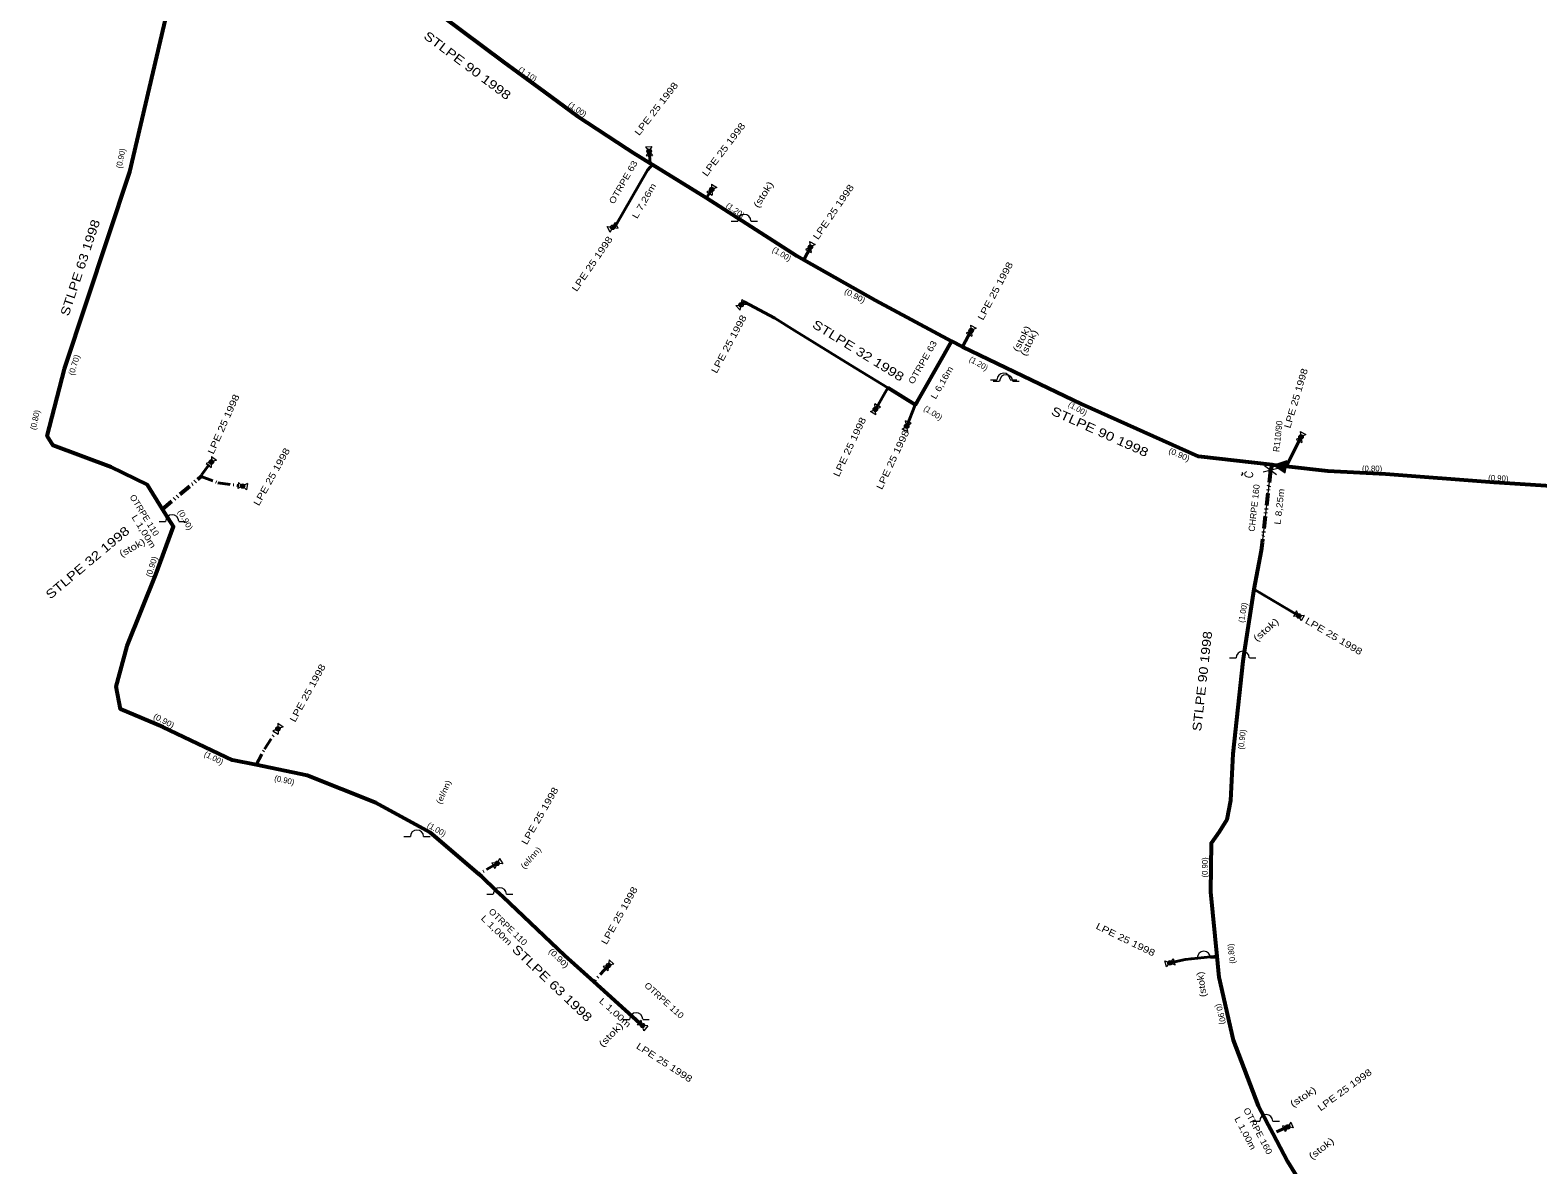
# Model space of a CAD drawing. Extents: x -648036 to -642998, y -1161549 to -1158141.
# Drawn here: x -646532.8 to -646363, y -1160970.1 to -1160842.2 of the extents above; entities that cross this region are included whole.
import ezdxf
from ezdxf.enums import TextEntityAlignment as Align

# ---------------------------------------------------------------- set-up
doc = ezdxf.new("R2010")
doc.units = 0
doc.header["$LTSCALE"] = 0.28
doc.linetypes.add('DASH_DOUBLE_DOT', pattern=[9.2, 5, -1.2, 0.3, -1.2, 0.3, -1.2])
for name, color, linetype, lineweight in [('12', 7, 'DASH_DOUBLE_DOT', 40), ('14', 7, 'Continuous', 13), ('15', 7, 'Continuous', 13), ('19', 7, 'Continuous', 13), ('8', 7, 'Continuous', 53)]:
    doc.layers.add(name, color=color, linetype=linetype, lineweight=lineweight)
for name, color, linetype in [('20', 7, 'Continuous'), ('22', 7, 'Continuous'), ('24', 7, 'Continuous'), ('25', 7, 'Continuous'), ('27', 7, 'Continuous'), ('28', 7, 'Continuous')]:
    doc.layers.add(name, color=color, linetype=linetype)

msp = doc.modelspace()

# ---------------------------------------------------------------- linework, layer by layer
at = {"layer": '12', "linetype": 'Continuous'}
for p, q in [((-646462.98, -1160857.21), (-646463.08, -1160855.87)), ((-646456.62, -1160861.15), (-646456.03, -1160860.2)), ((-646444.91, -1160866.68), (-646445.64, -1160868.12)), ((-646427.78, -1160877.92), (-646426.81, -1160876.1)), ((-646436.18, -1160882.55), (-646437.6, -1160884.97)), ((-646433.11, -1160884.48), (-646434.07, -1160886.86)), ((-646391.34, -1160891.4), (-646389.65, -1160888.08)), ((-646394.97, -1160905.24), (-646389.9, -1160908.26))]:
    msp.add_line(p, q, dxfattribs=at)
at = {"layer": '12'}
for p, q in [((-646480.19, -1160936.14), (-646482.27, -1160937.34)), ((-646467.65, -1160947.64), (-646469.3, -1160949.46)), ((-646464.09, -1160954.18), (-646463.83, -1160954.4)), ((-646391.13, -1160965.84), (-646392.83, -1160966.59))]:
    msp.add_line(p, q, dxfattribs=at)
at = {"layer": '12', "linetype": 'Continuous'}
for points in [[(-646462.7, -1160857.39), (-646463.26, -1160858), (-646466.87, -1160864.3), (-646467.19, -1160864.46)], [(-646436.18, -1160882.55), (-646440.44, -1160879.95), (-646446.71, -1160876.08), (-646448.94, -1160874.68), (-646452.36, -1160872.85), (-646452.72, -1160873.19)], [(-646399.14, -1160946.59), (-646402.7, -1160946.96), (-646404.41, -1160947.35)]]:
    msp.add_lwpolyline(points, dxfattribs=at)
at = {"layer": '12'}
for points in [[(-646513.52, -1160892.54), (-646513.47, -1160892.31), (-646512.39, -1160890.9)], [(-646513.52, -1160892.54), (-646511.67, -1160893.24), (-646508.87, -1160893.62)], [(-646507.36, -1160925.05), (-646506.41, -1160923.27), (-646504.89, -1160920.97)]]:
    msp.add_lwpolyline(points, dxfattribs=at)
at = {"layer": '14'}
for p, q in [((-646463.26, -1160858), (-646466.87, -1160864.3)), ((-646429.87, -1160878.82), (-646432.93, -1160884.17)), ((-646393.09, -1160891.84), (-646394.03, -1160900.03)), ((-646517.26, -1160897.24), (-646516.67, -1160898.18)), ((-646396.19, -1160913.36), (-646396.07, -1160912.3)), ((-646479.54, -1160939.9), (-646480.26, -1160939.22)), ((-646464.97, -1160953.38), (-646464.09, -1160954.18)), ((-646393.82, -1160964.73), (-646393.35, -1160965.61))]:
    msp.add_line(p, q, dxfattribs=at)
at = {"layer": '15'}
for p, q in [((-646463.473, -1160855.394), (-646462.762, -1160855.341)), ((-646463.473, -1160855.394), (-646462.687, -1160856.346)), ((-646462.762, -1160855.341), (-646463.398, -1160856.398)), ((-646463.398, -1160856.398), (-646462.687, -1160856.346)), ((-646455.462, -1160859.96), (-646456.598, -1160860.439)), ((-646456.067, -1160859.584), (-646455.993, -1160860.816)), ((-646456.067, -1160859.584), (-646455.462, -1160859.96)), ((-646456.598, -1160860.439), (-646455.993, -1160860.816)), ((-646453.835, -1160863.745), (-646453.1, -1160863.744)), ((-646451.614, -1160863.744), (-646450.88, -1160863.745)), ((-646467.8, -1160864.367), (-646466.581, -1160864.553)), ((-646467.482, -1160865.004), (-646467.8, -1160864.367)), ((-646467.482, -1160865.004), (-646466.898, -1160863.916)), ((-646466.581, -1160864.553), (-646466.898, -1160863.916)), ((-646444.365, -1160866.391), (-646445.455, -1160866.968)), ((-646445.455, -1160866.968), (-646444.82, -1160867.291)), ((-646445, -1160866.069), (-646444.82, -1160867.291)), ((-646445, -1160866.069), (-646444.365, -1160866.391)), ((-646453.331, -1160873.277), (-646452.11, -1160873.103)), ((-646452.842, -1160873.795), (-646453.331, -1160873.277)), ((-646452.842, -1160873.795), (-646452.598, -1160872.585)), ((-646452.11, -1160873.103), (-646452.598, -1160872.585)), ((-646426.887, -1160875.488), (-646426.733, -1160876.712)), ((-646426.887, -1160875.488), (-646426.259, -1160875.823)), ((-646426.259, -1160875.823), (-646427.361, -1160876.376)), ((-646427.361, -1160876.376), (-646426.733, -1160876.712)), ((-646424.635, -1160881.635), (-646423.9, -1160881.634)), ((-646424.345, -1160881.805), (-646423.61, -1160881.804)), ((-646422.414, -1160881.634), (-646421.68, -1160881.635)), ((-646422.124, -1160881.804), (-646421.39, -1160881.805)), ((-646438.162, -1160885.225), (-646437.038, -1160884.716)), ((-646437.548, -1160885.585), (-646438.162, -1160885.225)), ((-646437.038, -1160884.716), (-646437.652, -1160884.355)), ((-646437.548, -1160885.585), (-646437.652, -1160884.355)), ((-646434.589, -1160887.194), (-646433.552, -1160886.527)), ((-646433.928, -1160887.461), (-646434.589, -1160887.194)), ((-646433.552, -1160886.527), (-646434.212, -1160886.259)), ((-646433.928, -1160887.461), (-646434.212, -1160886.259)), ((-646389.739, -1160887.469), (-646389.561, -1160888.691)), ((-646389.739, -1160887.469), (-646389.104, -1160887.792)), ((-646389.104, -1160887.792), (-646390.195, -1160888.367)), ((-646390.195, -1160888.367), (-646389.561, -1160888.691)), ((-646511.801, -1160890.716), (-646512.978, -1160891.083)), ((-646512.366, -1160890.283), (-646512.414, -1160891.517)), ((-646512.366, -1160890.283), (-646511.801, -1160890.716)), ((-646512.978, -1160891.083), (-646512.414, -1160891.517)), ((-646396.376, -1160892.404), (-646396.199, -1160892.273)), ((-646396.322, -1160892.089), (-646396.199, -1160892.273)), ((-646392.278, -1160891.63), (-646393.901, -1160892.051)), ((-646392.43, -1160892.359), (-646393.749, -1160891.322)), ((-646509.321, -1160893.2), (-646509.417, -1160893.905)), ((-646508.323, -1160893.335), (-646509.417, -1160893.905)), ((-646508.418, -1160894.041), (-646509.321, -1160893.2)), ((-646508.323, -1160893.335), (-646508.418, -1160894.041)), ((-646518.285, -1160897.595), (-646517.55, -1160897.594)), ((-646516.064, -1160897.594), (-646515.33, -1160897.595)), ((-646390.15, -1160907.697), (-646390.515, -1160908.308)), ((-646389.649, -1160908.824), (-646390.15, -1160907.697)), ((-646389.285, -1160908.212), (-646390.515, -1160908.308)), ((-646389.285, -1160908.212), (-646389.649, -1160908.824)), ((-646397.695, -1160912.985), (-646396.96, -1160912.984)), ((-646395.474, -1160912.984), (-646394.74, -1160912.985)), ((-646504.315, -1160920.746), (-646505.464, -1160921.193)), ((-646505.464, -1160921.193), (-646504.871, -1160921.587)), ((-646504.909, -1160920.353), (-646504.871, -1160921.587)), ((-646504.909, -1160920.353), (-646504.315, -1160920.746)), ((-646490.705, -1160933.125), (-646489.97, -1160933.124)), ((-646488.484, -1160933.124), (-646487.75, -1160933.125)), ((-646480.804, -1160936.083), (-646480.449, -1160936.7)), ((-646479.576, -1160936.197), (-646480.804, -1160936.083)), ((-646479.931, -1160935.58), (-646480.449, -1160936.7)), ((-646479.931, -1160935.58), (-646479.576, -1160936.197)), ((-646481.375, -1160939.625), (-646480.64, -1160939.624)), ((-646479.154, -1160939.624), (-646478.42, -1160939.625)), ((-646404.822, -1160947.809), (-646403.998, -1160946.891)), ((-646403.84, -1160947.585), (-646403.998, -1160946.891)), ((-646402.075, -1160946.795), (-646401.34, -1160946.794)), ((-646399.854, -1160946.794), (-646399.12, -1160946.795)), ((-646467.048, -1160947.506), (-646468.252, -1160947.774)), ((-646468.252, -1160947.774), (-646467.725, -1160948.253)), ((-646467.575, -1160947.027), (-646467.725, -1160948.253)), ((-646467.575, -1160947.027), (-646467.048, -1160947.506)), ((-646404.981, -1160947.115), (-646403.84, -1160947.585)), ((-646404.822, -1160947.809), (-646404.981, -1160947.115)), ((-646466.025, -1160953.725), (-646465.29, -1160953.724)), ((-646463.804, -1160953.724), (-646463.07, -1160953.725)), ((-646463.984, -1160953.803), (-646464.445, -1160954.346)), ((-646463.215, -1160954.454), (-646464.445, -1160954.346)), ((-646463.675, -1160954.997), (-646463.984, -1160953.803)), ((-646463.215, -1160954.454), (-646463.675, -1160954.997)), ((-646395.045, -1160965.195), (-646394.31, -1160965.194)), ((-646392.824, -1160965.194), (-646392.09, -1160965.195)), ((-646390.813, -1160965.311), (-646391.447, -1160966.369)), ((-646390.813, -1160965.311), (-646390.525, -1160965.962)), ((-646391.734, -1160965.717), (-646391.447, -1160966.369)), ((-646390.525, -1160965.962), (-646391.734, -1160965.717))]:
    msp.add_line(p, q, dxfattribs=at)
for points in [[(-646391.234, -1160890.776), (-646392.7, -1160891.25), (-646391.437, -1160892.134), (-646391.335, -1160891.455)], [(-646391.356, -1160890.921), (-646392.477, -1160891.283), (-646391.512, -1160891.959)], [(-646391.479, -1160891.067), (-646392.256, -1160891.318), (-646391.587, -1160891.785)], [(-646391.602, -1160891.211), (-646392.034, -1160891.351), (-646391.662, -1160891.61)]]:
    msp.add_lwpolyline(points, close=True, dxfattribs=at)
for centre in [(-646452.3574, -1160863.7446), (-646423.1574, -1160881.6346), (-646422.8674, -1160881.8046), (-646516.8074, -1160897.5946), (-646396.2174, -1160912.9846), (-646489.2274, -1160933.1246), (-646479.8974, -1160939.6246), (-646400.5974, -1160946.7946), (-646464.5474, -1160953.7246), (-646393.5674, -1160965.1946)]:
    msp.add_arc(centre, 0.7431, 1.2748, 179.83951, dxfattribs=at)
at = {"layer": '19'}
for centre, radius in [((-646463.08, -1160855.87), 0.25), ((-646463.08, -1160855.87), 0.17), ((-646463.08, -1160855.87), 0.09), ((-646456.03, -1160860.2), 0.25), ((-646456.03, -1160860.2), 0.17), ((-646456.03, -1160860.2), 0.09), ((-646467.19, -1160864.46), 0.25), ((-646467.19, -1160864.46), 0.17), ((-646467.19, -1160864.46), 0.09), ((-646444.91, -1160866.68), 0.25), ((-646444.91, -1160866.68), 0.17), ((-646444.91, -1160866.68), 0.09), ((-646452.72, -1160873.19), 0.25), ((-646452.72, -1160873.19), 0.17), ((-646452.72, -1160873.19), 0.09), ((-646426.81, -1160876.1), 0.25), ((-646426.81, -1160876.1), 0.17), ((-646426.81, -1160876.1), 0.09), ((-646437.6, -1160884.97), 0.25), ((-646437.6, -1160884.97), 0.17), ((-646437.6, -1160884.97), 0.09), ((-646434.07, -1160886.86), 0.25), ((-646434.07, -1160886.86), 0.17), ((-646434.07, -1160886.86), 0.09), ((-646389.65, -1160888.08), 0.25), ((-646389.65, -1160888.08), 0.17), ((-646389.65, -1160888.08), 0.09), ((-646512.39, -1160890.9), 0.25), ((-646512.39, -1160890.9), 0.17), ((-646512.39, -1160890.9), 0.09), ((-646508.87, -1160893.62), 0.25), ((-646508.87, -1160893.62), 0.17), ((-646508.87, -1160893.62), 0.09), ((-646389.9, -1160908.26), 0.25), ((-646389.9, -1160908.26), 0.17), ((-646389.9, -1160908.26), 0.09), ((-646504.89, -1160920.97), 0.25), ((-646504.89, -1160920.97), 0.17), ((-646504.89, -1160920.97), 0.09), ((-646480.19, -1160936.14), 0.25), ((-646480.19, -1160936.14), 0.17), ((-646480.19, -1160936.14), 0.09), ((-646467.65, -1160947.64), 0.25), ((-646467.65, -1160947.64), 0.17), ((-646467.65, -1160947.64), 0.09), ((-646404.41, -1160947.35), 0.25), ((-646404.41, -1160947.35), 0.17), ((-646404.41, -1160947.35), 0.09), ((-646463.83, -1160954.4), 0.25), ((-646463.83, -1160954.4), 0.17), ((-646463.83, -1160954.4), 0.09), ((-646391.13, -1160965.84), 0.25), ((-646391.13, -1160965.84), 0.17), ((-646391.13, -1160965.84), 0.09)]:
    msp.add_circle(centre, radius, dxfattribs=at)
at = {"layer": '8', "linetype": 'DASH_DOUBLE_DOT'}
for p, q in [((-646517.9, -1160896.21), (-646513.52, -1160892.54)), ((-646392.9, -1160891.22), (-646393.09, -1160891.84))]:
    msp.add_line(p, q, dxfattribs=at)
at = {"layer": '8'}
for p, q in [((-646392.7, -1160891.25), (-646392.9, -1160891.22)), ((-646394.13, -1160900.87), (-646394.97, -1160905.24))]:
    msp.add_line(p, q, dxfattribs=at)
for points in [[(-646517.9, -1160896.21), (-646519.6, -1160893.48), (-646523.67, -1160891.49), (-646530.21, -1160889.05), (-646530.87, -1160887.95), (-646528.92, -1160880.39), (-646521.56, -1160858.21), (-646516.32, -1160835.7), (-646514.98, -1160833.83), (-646512.81, -1160830.8), (-646508.28, -1160823.84), (-646507.06, -1160822.64)], [(-646490.53, -1160837.2), (-646486.43, -1160840.62), (-646479.5, -1160845.82), (-646474.88, -1160849.19), (-646471.13, -1160851.92), (-646465.59, -1160855.57), (-646464.83, -1160856.07), (-646462.98, -1160857.21), (-646462.7, -1160857.39)], [(-646462.7, -1160857.39), (-646458.37, -1160860.05), (-646456.62, -1160861.15)], [(-646456.62, -1160861.15), (-646453.15, -1160863.34), (-646446.45, -1160867.67), (-646445.64, -1160868.12)], [(-646445.64, -1160868.12), (-646437.61, -1160872.65), (-646429.03, -1160877.3)], [(-646429.03, -1160877.3), (-646429.87, -1160878.82), (-646432.93, -1160884.17), (-646433.11, -1160884.48), (-646436.18, -1160882.55)], [(-646392.9, -1160891.22), (-646401.21, -1160890.3), (-646414.33, -1160884.39), (-646421.91, -1160880.76), (-646427.78, -1160877.92), (-646429.03, -1160877.3)], [(-646359.15, -1160893.78), (-646367.91, -1160893.23), (-646380.15, -1160892.26), (-646386.62, -1160891.92), (-646391.34, -1160891.4), (-646392.7, -1160891.25)], [(-646507.36, -1160925.05), (-646510.02, -1160924.5), (-646517.82, -1160920.78), (-646522.63, -1160918.75), (-646523.13, -1160916.19), (-646521.88, -1160911.62), (-646518.63, -1160903.57), (-646516.67, -1160898.18), (-646517.26, -1160897.24), (-646517.9, -1160896.21)], [(-646394.97, -1160905.24), (-646396.07, -1160912.3), (-646396.19, -1160913.36), (-646397.33, -1160923.79), (-646397.6, -1160929.07), (-646398.02, -1160931.18), (-646398.86, -1160932.59), (-646399.76, -1160933.85), (-646399.83, -1160939.33), (-646399.14, -1160946.59)], [(-646482.27, -1160937.34), (-646487.76, -1160932.66), (-646493.85, -1160929.31), (-646501.61, -1160926.24), (-646507.36, -1160925.05)], [(-646469.3, -1160949.46), (-646472.57, -1160946.51), (-646479.54, -1160939.9), (-646480.26, -1160939.22), (-646481.93, -1160937.63), (-646482.27, -1160937.34)], [(-646399.14, -1160946.59), (-646398.91, -1160948.97), (-646397.3, -1160956.05), (-646394.48, -1160963.47), (-646393.82, -1160964.73), (-646393.35, -1160965.61), (-646392.83, -1160966.59)], [(-646464.09, -1160954.18), (-646464.97, -1160953.38), (-646469.3, -1160949.46)], [(-646392.83, -1160966.59), (-646391.17, -1160969.75), (-646390.39, -1160971.02), (-646389.87, -1160971.88), (-646387.23, -1160976.21), (-646387.22, -1160976.24)]]:
    msp.add_lwpolyline(points, dxfattribs=at)
at = {"layer": '8', "linetype": 'DASH_DOUBLE_DOT'}
msp.add_lwpolyline([(-646393.09, -1160891.84), (-646394.03, -1160900.03), (-646394.13, -1160900.87)], dxfattribs=at)

# ---------------------------------------------------------------- texts
at = {"layer": '15', "width": 0.8}
msp.add_text('C', height=1, rotation=80.214, dxfattribs=at).set_placement((-646395.0526, -1160892.413), align=Align.CENTER)
at = {"layer": '20'}
for s, rotation, width, p in [('STLPE 90 1998', 323.148, 1.25, (-646483.8464, -1160846.6199)), ('STLPE 63 1998', 71.62, 1.2, (-646526.6931, -1160869.1592)), ('STLPE 32 1998', 328.305, 1.25, (-646439.7867, -1160878.7694)), ('STLPE 90 1998', 335.753, 1.25, (-646412.5113, -1160887.9455)), ('STLPE 32 1998', 40.107, 1.25, (-646526.0156, -1160902.6283)), ('STLPE 90 1998', 83.652, 1.2, (-646400.2832, -1160915.6608)), ('STLPE 63 1998', 316.273, 1.25, (-646474.3441, -1160950.0144))]:
    msp.add_text(s, height=1, rotation=rotation, dxfattribs=dict(at, width=width)).set_placement(p, align=Align.CENTER)
at = {"layer": '22'}
for rotation, width, p in [(52.139, 1.25, (-646461.9826, -1160851.3252)), (52.712, 1.25, (-646454.3857, -1160855.9107)), (55.577, 1.25, (-646442.0108, -1160862.934)), (55.577, 1.25, (-646469.1908, -1160868.784)), (61.879, 1.25, (-646423.7629, -1160871.8072)), (61.879, 1.25, (-646453.7729, -1160877.7872)), (73.339, 1.2, (-646389.8675, -1160883.831)), (65.89, 1.25, (-646510.6784, -1160886.7902)), (64.744, 1.25, (-646440.1568, -1160889.371)), (64.744, 1.25, (-646435.3068, -1160890.811)), (60.734, 1.25, (-646505.269, -1160892.7573)), (329.451, 1.25, (-646386.1481, -1160910.8546)), (61.306, 1.25, (-646501.2209, -1160917.122)), (60.161, 1.25, (-646475.0673, -1160930.9731)), (60.734, 1.25, (-646466.109, -1160942.2073)), (334.034, 1.25, (-646409.5747, -1160945.0538)), (327.159, 1.25, (-646461.5674, -1160958.8923)), (36.096, 1.25, (-646384.5204, -1160961.972))]:
    msp.add_text('LPE 25 1998', height=0.75, rotation=rotation, dxfattribs=dict(at, width=width)).set_placement(p, align=Align.CENTER)
at = {"layer": '24'}
for s, rotation, width, p in [('OTRPE 63', 60.161, 1.2, (-646465.6978, -1160859.5442)), ('L 7,26m', 60.161, 1.3, (-646463.3435, -1160861.6432)), ('OTRPE 63', 60.161, 1.2, (-646431.9778, -1160879.8442)), ('L 6,16m', 60.161, 1.2, (-646429.7957, -1160882.1287)), ('CHRPE 160', 83.652, 1.05, (-646394.5904, -1160896.1207)), ('L 8,25m', 83.652, 1.2, (-646391.7465, -1160895.9697)), ('OTRPE 110', 301.949, 1.05, (-646520.2215, -1160897.0853)), ('L 1,00m', 301.949, 1.25, (-646520.2885, -1160898.9108)), ('OTRPE 110', 316.273, 1.1, (-646479.2149, -1160943.5516)), ('L 1,00m', 316.273, 1.3, (-646480.5024, -1160943.9317)), ('OTRPE 110', 317.992, 1.1, (-646461.6182, -1160951.8477)), ('L 1,00m', 317.992, 1.3, (-646467.1437, -1160953.2145)), ('OTRPE 160', 297.938, 1.15, (-646394.8176, -1160966.464)), ('L 1,00m', 297.938, 1.2, (-646396.2374, -1160966.705))]:
    msp.add_text(s, height=0.7, rotation=rotation, dxfattribs=dict(at, width=width)).set_placement(p, align=Align.CENTER)
at = {"layer": '25'}
msp.add_text('R110/90', height=0.7, rotation=83.652, dxfattribs=at).set_placement((-646391.9158, -1160888.0452), align=Align.CENTER)
at = {"layer": '27'}
for s, rotation, p in [('(1.10)', 326.586, (-646476.9425, -1160847.4652)), ('(1.00)', 326.013, (-646471.3367, -1160851.4289)), ('(0.90)', 79.068, (-646522.2781, -1160856.7406)), ('(1.20)', 324.867, (-646453.5735, -1160862.7885)), ('(1.00)', 328.878, (-646448.3045, -1160867.7347)), ('(1.20)', 330.597, (-646426.1221, -1160880.0838)), ('(1.00)', 330.597, (-646414.9656, -1160885.1786)), ('(0.80)', 77.349, (-646531.9303, -1160886.2272)), ('(1.00)', 327.732, (-646431.2675, -1160885.6409)), ('(0.90)', 357.526, (-646367.4405, -1160893.0458)), ('(1.00)', 79.641, (-646395.8898, -1160907.9354)), ('(0.90)', 83.652, (-646395.988, -1160922.2079)), ('(1.00)', 332.316, (-646512.2665, -1160924.5413)), ('(0.90)', 347.785, (-646504.2333, -1160927.0725)), ('(1.00)', 330.024, (-646487.1724, -1160932.59)), ('(0.90)', 89.954, (-646400.16, -1160936.5943)), ('(0.80)', 97.403, (-646397.1699, -1160946.2789))]:
    msp.add_text(s, height=0.65, rotation=rotation, dxfattribs=at).set_placement(p, align=Align.CENTER)
for s, rotation, width, p in [('(0.90)', 332.316, 1.1, (-646440.052, -1160872.4502)), ('(0.70)', 73.339, 1.05, (-646527.5383, -1160880.0662)), ('(0.90)', 336.326, 1.1, (-646403.4955, -1160890.3653)), ('(0.90)', 299.657, 1.1, (-646515.6, -1160897.5797)), ('(0.90)', 71.62, 1.05, (-646518.8092, -1160902.7965)), ('(0.90)', 332.316, 1.1, (-646517.892, -1160920.3502)), ('(el/nn)', 65.317, 1.15, (-646485.9354, -1160928.2342)), ('(el/nn)', 48.701, 1.2, (-646476.151, -1160935.7285)), ('(0.90)', 315.7, 1.2, (-646473.488, -1160947.048)), ('(0.90)', 284.187, 1.05, (-646398.9857, -1160953.1983))]:
    msp.add_text(s, height=0.65, rotation=rotation, dxfattribs=dict(at, width=width)).set_placement(p, align=Align.CENTER)
msp.add_text('(0.80)', height=0.65, dxfattribs=at).set_placement((-646381.65, -1160891.96), align=Align.CENTER)
at = {"layer": '28'}
for rotation, width, p in [(57.869, 1.3, (-646449.8997, -1160860.9614)), (62.452, 1.25, (-646420.7842, -1160877.1819)), (63.025, 1.25, (-646419.9592, -1160877.6341)), (29.221, 1.25, (-646521.1346, -1160900.8791)), (40.68, 1.35, (-646393.3584, -1160910.0884)), (97.976, 1.15, (-646400.4964, -1160949.729)), (45.837, 1.35, (-646467.1279, -1160955.7078)), (33.805, 1.3, (-646389.2136, -1160962.752)), (37.815, 1.3, (-646387.1389, -1160968.5644))]:
    msp.add_text('(stok)', height=0.75, rotation=rotation, dxfattribs=dict(at, width=width)).set_placement(p, align=Align.CENTER)

doc.saveas('drawing.dxf')
